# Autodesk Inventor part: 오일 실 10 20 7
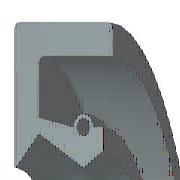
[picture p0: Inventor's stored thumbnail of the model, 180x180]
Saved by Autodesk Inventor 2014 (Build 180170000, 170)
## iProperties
IsCustomPart: 1
Created: 2012-02
Part Number: 오일 실 10 20 7
Material: 고무
Description: 오일-실
Document SubType Name: Modeling
Standard: KS B 2804
Designer: mduedu
Standards Organization: KS
Language: ko-KR
Size Designation: D - 10 20 7
Categories: <MemberInstance><Categories><Category DisplayName="샤프트 부품" InternalName="7f7aeb1f-a693-4053-b835-cee3144e0d98" Mnemonic="SHFT"><Category DisplayName="실링" Intern
Density: 0.93 g/cm^3
Appearance: Rubber - Black - Version 1.1
Author: mduedu
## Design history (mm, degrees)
revolve "본체" stored, may be unused: angle "d17" = 90 deg
revolve "스프링1" stored, may be unused: angle "d18" = 90 deg
body "Solid1"
sketch "스케치1"
  geometry: L1 (0, 10)-(7, 10); L2 (7, 8.25)-(1.75, 8.25); L3 (1.75, 6.75)-(4.9, 5); L4 (4.9, 5)-(0, 5); L5 (0, 0)-(9.586, 0) reference; L6 (4.9, 5)-(6.3, 5.875); L7 (0, 18)-(0, -3) reference; L8 (-1.941, 0)-(11.507, 0) reference; L9 (4.2, 7.1)-(1.75, 7.59); L10 (1.75, 7.59)-(1.75, 8.25); L11 (0, 10)-(0, 5.088); L12 (4.9, 5)-(0, 5); L13 (1.75, 6.75)-(0.152, 5.028); L14 (7, 10)-(7, 8.25); L15 (5.6, 7.1)-(6.3, 7.1); L16 (6.3, 7.1)-(6.3, 5.875); C1 r 0.455 at (4.9, 7.1); A1 r 0.7 centre (4.9, 7.1) between (5.6, 7.1) and (4.2, 7.1); A2 r 0.088 centre (0.088, 5.088) between (0, 5.088) and (0.152, 5.028); 1 further point
  constraints: 28 end point, 5 horizontal alignment, 5 point on line, 4 point on circle, 4 vertical alignment, 3 centre point, 3 tangent, 2 collinear, 2 horizontal, 2 perpendicular, 1 coincident, 1 parallel
  dimensions: "d0" = 20 diameter of L1 L5 (= SD2); "d1" = 1.75 distance of L1.end L2.start (= SD); "d2" = 0.91 diameter of C1 (= SPDI); "d3" = 1.4 diameter of A1 (= SPDA); "d4" = 10 diameter of L3.end L5 (= NND); "d5" = 13.5 diameter of L3.start L5 (= TKDM); "d7" = 15.18 diameter of L9.end L5 (= TKDM + 0.24 x SWDT); "d8" = 1.75 distance between parallel lines of L11 L10 (= SD); "d9" = 4.9 distance from line of L11 C1.centre (= SPDST); "d10" = 14.2 diameter of C1.centre L5 (= HLDM); "d11" = 0.0875 radius of A2 (= 0.25 x LAB); "d12" = 6.3 distance between parallel lines of L11 L16 (= SDI); "d13" = 11.75 diameter of L6.end L5 (= ABDM); "d14" = 7 distance from line of L11 L1.end (= SWDT)
fillet "모깎기1" dims "d6" = 0.3 (= RR)
other parameters: "SD2" = 20 [user parameter; used in 1 equation term], "SWDT" = 7 [user parameter; used in 2 equation terms], "RR" = 0.3 [user parameter; used in 1 equation term], "SD" = 1.75 [user parameter; used in 2 equation terms], "NND" = 10 [user parameter; used in 1 equation term], "SPDA" = 1.4 [user parameter; used in 1 equation term], "SPDI" = 0.91 [user parameter; used in 1 equation term], "TKDM" = 13.5 [user parameter; used in 2 equation terms], "HLDM" = 14.2 [user parameter; used in 1 equation term], "ABDM" = 11.75 [user parameter; used in 1 equation term], "SDI" = 6.3 [user parameter; used in 1 equation term], "SPDST" = 4.9 [user parameter; used in 1 equation term], "LAB" = 0.35 [user parameter; used in 1 equation term], "d15" = 0, "d16" = 0, "d19" = 0
